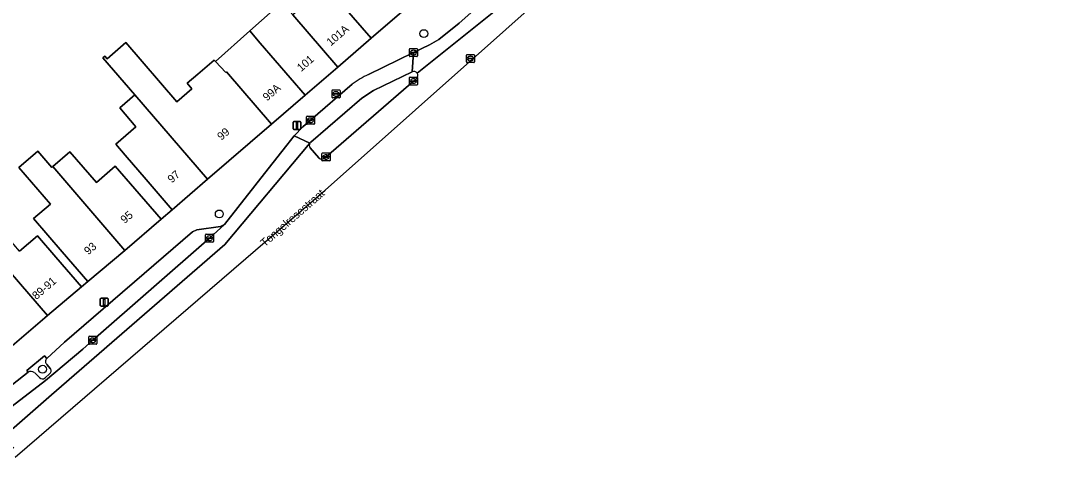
# Model space of a CAD drawing. Extents: x 161772 to 163126, y 383092 to 383917.
# Drawn here: x 162534.3 to 162665.1, y 383408.5 to 383464.9 of the extents above; entities that cross this region are included whole.
import ezdxf

# ---------------------------------------------------------------- set-up
doc = ezdxf.new("R2010")
doc.units = 0
for name, color, linetype in [('IMGEO_Boom', 7, 'Continuous'), ('IMGEO_Brandkraan', 7, 'Continuous'), ('IMGEO_Erf', 7, 'Continuous'), ('IMGEO_Fietspad_gesloten', 7, 'Continuous'), ('IMGEO_Kolk', 7, 'Continuous'), ('IMGEO_Lichtmast', 7, 'Continuous'), ('IMGEO_Openbare_ruimte_label', 7, 'Continuous'), ('IMGEO_Pand', 7, 'Continuous'), ('IMGEO_Pand_nummerreeks', 7, 'Continuous'), ('IMGEO_Parkeervlak_open', 7, 'Continuous'), ('IMGEO_Rijbaan_lokaal_gesloten', 7, 'Continuous'), ('IMGEO_Rioolput', 7, 'Continuous'), ('IMGEO_Verkeerseiland_groen', 7, 'Continuous'), ('IMGEO_Verkeerseiland_open', 7, 'Continuous'), ('IMGEO_Voetpad_open', 7, 'Continuous')]:
    doc.layers.add(name, color=color, linetype=linetype)

msp = doc.modelspace()

# ---------------------------------------------------------------- linework, layer by layer
at = {"layer": 'IMGEO_Boom'}
for centre in [(162584.63, 383463.28), (162559.08, 383440.74), (162537.01, 383421.33)]:
    msp.add_circle(centre, 0.489, dxfattribs=at)
at = {"layer": 'IMGEO_Brandkraan'}
for p, q in [((162573.23, 383456.24), (162574.09, 383456.24)), ((162573.16, 383455.31), (162573.16, 383456.17)), ((162574.09, 383455.24), (162573.23, 383455.24)), ((162573.42, 383455.73), (162573.42, 383455.75)), ((162573.46, 383455.78), (162573.86, 383455.78)), ((162573.86, 383455.7), (162573.46, 383455.7)), ((162573.67, 383455.46), (162573.64, 383455.46)), ((162573.65, 383456.02), (162573.67, 383456.02)), ((162573.9, 383455.75), (162573.9, 383455.73)), ((162574.16, 383456.17), (162574.16, 383455.31))]:
    msp.add_line(p, q, dxfattribs=at)
for points in [[(162573.23, 383456.24), (162574.09, 383456.24)], [(162573.16, 383455.31), (162573.16, 383456.17)], [(162574.09, 383455.24), (162573.23, 383455.24)], [(162574.16, 383456.17), (162574.16, 383455.31)]]:
    msp.add_lwpolyline(points, dxfattribs=at)
for centre, radius, start, end in [((162573.24, 383456.17), 0.0765, 91.552, 178.448), ((162573.24, 383456.17), 0.0765, 91.552, 178.448), ((162574.08, 383456.17), 0.0765, 1.552, 88.448), ((162574.08, 383456.17), 0.0765, 1.552, 88.448), ((162573.24, 383455.32), 0.0765, 181.552, 268.448), ((162573.24, 383455.32), 0.0765, 181.552, 268.448), ((162573.46, 383455.74), 0.0403, 85.8775, 175.7526), ((162573.45, 383455.73), 0.0366, 178.938, 274.7102), ((162573.86, 383455.75), 0.0386, 1.7309, 96.639), ((162573.86, 383455.74), 0.043, 264.8664, 352.4533), ((162574.08, 383455.32), 0.0765, 271.552, 358.448), ((162574.08, 383455.32), 0.0765, 271.552, 358.448)]:
    msp.add_arc(centre, radius, start, end, dxfattribs=at)
for centre, major_axis, ratio, start_param, end_param in [((162573.65, 383455.74), (-0.387, 0.002), 0.722429, 4.712389, 7.853982), ((162573.67, 383455.74), (-0.39, 0.002), 0.717154, 1.570796, 4.712389)]:
    msp.add_ellipse(centre, major_axis=major_axis, ratio=ratio, start_param=start_param, end_param=end_param, dxfattribs=at)
at = {"layer": 'IMGEO_Erf'}
msp.add_lwpolyline([(162534.15, 383436.08), (162536.38, 383438), (162538.67, 383435.33), (162541.88, 383431.61), (162542.68, 383432.29), (162539.46, 383436.02), (162535.89, 383440.16), (162538, 383441.98), (162534.06, 383446.56), (162536.41, 383448.58), (162538.15, 383446.56), (162538.29, 383446.67), (162540.41, 383448.51), (162543.73, 383444.66), (162546.09, 383446.7), (162548.55, 383443.86), (162551.81, 383440.07), (162553.21, 383441.27), (162549.95, 383445.06), (162547.33, 383448.1), (162546.15, 383449.47), (162548.67, 383451.64), (162546.65, 383453.99), (162548.53, 383455.61), (162544.54, 383460.24), (162544.78, 383460.45), (162545.07, 383460.11), (162547.43, 383462.15), (162553.8, 383454.76), (162555.67, 383456.36), (162555.07, 383457.07), (162556.41, 383458.22), (162558.43, 383459.96), (162558.59, 383459.8), (162562.88, 383463.61), (162566.9, 383467.17)], dxfattribs=at)
at = {"layer": 'IMGEO_Fietspad_gesloten'}
for points in [[(162576.89, 383455.22), (162578.35, 383456.17), (162583.17, 383458.49), (162583.33, 383460.91), (162577.72, 383458.18)], [(162575.68, 383456.95), (162570.47, 383452.45), (162569.53, 383451.63), (162568.44, 383450.5), (162570.38, 383449.58)], [(162570.5, 383449.72), (162576.89, 383455.22)]]:
    msp.add_lwpolyline(points, dxfattribs=at)
for centre, radius, start, end in [((162583.4, 383446.48), 13.01, 115.8975, 126.3933), ((162570.81, 383449.34), 0.489, 129.2025, 150.6211)]:
    msp.add_arc(centre, radius, start, end, dxfattribs=at)
at = {"layer": 'IMGEO_Kolk'}
for p, q in [((162582.83, 383460.48), (162582.83, 383461.33)), ((162582.9, 383461.41), (162583.76, 383461.41)), ((162583.76, 383460.41), (162582.9, 383460.41)), ((162583.09, 383460.9), (162583.09, 383460.91)), ((162583.13, 383460.95), (162583.53, 383460.95)), ((162583.52, 383460.86), (162583.13, 383460.86)), ((162583.34, 383460.63), (162583.31, 383460.63)), ((162583.32, 383461.19), (162583.34, 383461.19)), ((162583.57, 383460.91), (162583.57, 383460.9)), ((162583.83, 383461.33), (162583.83, 383460.48)), ((162582.84, 383456.92), (162582.84, 383457.78)), ((162582.91, 383457.85), (162583.77, 383457.85)), ((162583.33, 383457.63), (162583.35, 383457.63)), ((162583.84, 383457.78), (162583.84, 383456.92)), ((162583.77, 383456.85), (162582.91, 383456.85)), ((162583.1, 383457.34), (162583.1, 383457.36)), ((162583.14, 383457.39), (162583.54, 383457.39)), ((162583.54, 383457.31), (162583.14, 383457.31)), ((162583.35, 383457.07), (162583.33, 383457.07)), ((162583.58, 383457.36), (162583.58, 383457.34)), ((162569.96, 383452.02), (162569.96, 383452.87)), ((162570.04, 383452.95), (162570.89, 383452.95)), ((162570.22, 383452.44), (162570.22, 383452.45)), ((162570.66, 383452.4), (162570.26, 383452.4)), ((162570.27, 383452.49), (162570.66, 383452.49)), ((162570.45, 383452.73), (162570.48, 383452.73)), ((162570.71, 383452.45), (162570.71, 383452.44)), ((162570.97, 383452.87), (162570.97, 383452.02)), ((162570.89, 383451.95), (162570.04, 383451.95)), ((162570.47, 383452.17), (162570.45, 383452.17)), ((162571.91, 383447.43), (162571.91, 383448.28)), ((162571.99, 383448.36), (162572.84, 383448.36)), ((162572.84, 383447.36), (162571.99, 383447.36)), ((162572.17, 383447.85), (162572.17, 383447.86)), ((162572.21, 383447.9), (162572.61, 383447.9)), ((162572.61, 383447.81), (162572.21, 383447.81)), ((162572.4, 383448.14), (162572.43, 383448.14)), ((162572.42, 383447.58), (162572.4, 383447.58)), ((162572.66, 383447.86), (162572.66, 383447.85)), ((162572.91, 383448.28), (162572.91, 383447.43)), ((162557.36, 383437.28), (162557.36, 383438.14)), ((162557.44, 383438.21), (162558.29, 383438.21)), ((162557.85, 383437.99), (162557.88, 383437.99)), ((162558.36, 383438.14), (162558.36, 383437.28)), ((162558.29, 383437.21), (162557.44, 383437.21)), ((162557.62, 383437.7), (162557.62, 383437.72)), ((162558.06, 383437.67), (162557.66, 383437.67)), ((162557.67, 383437.75), (162558.06, 383437.75)), ((162557.87, 383437.43), (162557.85, 383437.43)), ((162558.11, 383437.72), (162558.11, 383437.7)), ((162542.78, 383424.53), (162542.78, 383425.38)), ((162542.86, 383425.45), (162543.71, 383425.45)), ((162543.04, 383424.95), (162543.04, 383424.96)), ((162543.48, 383424.91), (162543.08, 383424.91)), ((162543.09, 383425), (162543.48, 383425)), ((162543.27, 383425.23), (162543.3, 383425.23)), ((162543.53, 383424.96), (162543.53, 383424.95)), ((162543.78, 383425.38), (162543.78, 383424.53)), ((162543.71, 383424.45), (162542.86, 383424.45)), ((162543.29, 383424.67), (162543.27, 383424.67))]:
    msp.add_line(p, q, dxfattribs=at)
for points in [[(162582.83, 383460.48), (162582.83, 383461.33)], [(162582.9, 383461.41), (162583.76, 383461.41)], [(162583.76, 383460.41), (162582.9, 383460.41)], [(162583.83, 383461.33), (162583.83, 383460.48)], [(162582.84, 383456.92), (162582.84, 383457.78)], [(162582.91, 383457.85), (162583.77, 383457.85)], [(162583.84, 383457.78), (162583.84, 383456.92)], [(162583.77, 383456.85), (162582.91, 383456.85)], [(162569.96, 383452.02), (162569.96, 383452.87)], [(162570.04, 383452.95), (162570.89, 383452.95)], [(162570.97, 383452.87), (162570.97, 383452.02)], [(162570.89, 383451.95), (162570.04, 383451.95)], [(162571.91, 383447.43), (162571.91, 383448.28)], [(162571.99, 383448.36), (162572.84, 383448.36)], [(162572.84, 383447.36), (162571.99, 383447.36)], [(162572.91, 383448.28), (162572.91, 383447.43)], [(162557.36, 383437.28), (162557.36, 383438.14)], [(162557.44, 383438.21), (162558.29, 383438.21)], [(162558.36, 383438.14), (162558.36, 383437.28)], [(162558.29, 383437.21), (162557.44, 383437.21)], [(162542.78, 383424.53), (162542.78, 383425.38)], [(162542.86, 383425.45), (162543.71, 383425.45)], [(162543.78, 383425.38), (162543.78, 383424.53)], [(162543.71, 383424.45), (162542.86, 383424.45)]]:
    msp.add_lwpolyline(points, dxfattribs=at)
for centre, radius, start, end in [((162582.9, 383461.33), 0.0765, 91.552, 178.448), ((162582.9, 383461.33), 0.0765, 91.552, 178.448), ((162582.9, 383460.48), 0.0765, 181.552, 268.448), ((162582.9, 383460.48), 0.0765, 181.552, 268.448), ((162583.13, 383460.91), 0.0403, 85.8775, 175.7526), ((162583.12, 383460.9), 0.0366, 178.938, 274.7102), ((162583.53, 383460.91), 0.043, 264.8664, 352.4533), ((162583.53, 383460.91), 0.0386, 1.7309, 96.639), ((162583.75, 383461.33), 0.0765, 1.552, 88.448), ((162583.75, 383461.33), 0.0765, 1.552, 88.448), ((162583.75, 383460.48), 0.0765, 271.552, 358.448), ((162583.75, 383460.48), 0.0765, 271.552, 358.448), ((162582.92, 383457.77), 0.0765, 91.552, 178.448), ((162582.92, 383457.77), 0.0765, 91.552, 178.448), ((162583.76, 383457.77), 0.0765, 1.552, 88.448), ((162583.76, 383457.77), 0.0765, 1.552, 88.448), ((162582.92, 383456.92), 0.0765, 181.552, 268.448), ((162582.92, 383456.92), 0.0765, 181.552, 268.448), ((162583.14, 383457.35), 0.0403, 85.8775, 175.7526), ((162583.14, 383457.34), 0.0366, 178.938, 274.7102), ((162583.54, 383457.35), 0.0386, 1.7309, 96.639), ((162583.54, 383457.35), 0.043, 264.8664, 352.4533), ((162583.76, 383456.92), 0.0765, 271.552, 358.448), ((162583.76, 383456.92), 0.0765, 271.552, 358.448), ((162570.04, 383452.87), 0.0765, 91.552, 178.448), ((162570.04, 383452.87), 0.0765, 91.552, 178.448), ((162570.26, 383452.45), 0.0403, 85.8775, 175.7526), ((162570.26, 383452.44), 0.0366, 178.938, 274.7102), ((162570.67, 383452.45), 0.0386, 1.7309, 96.639), ((162570.66, 383452.45), 0.043, 264.8664, 352.4533), ((162570.89, 383452.87), 0.0765, 1.552, 88.448), ((162570.89, 383452.87), 0.0765, 1.552, 88.448), ((162570.04, 383452.02), 0.0765, 181.552, 268.448), ((162570.04, 383452.02), 0.0765, 181.552, 268.448), ((162570.89, 383452.02), 0.0765, 271.552, 358.448), ((162570.89, 383452.02), 0.0765, 271.552, 358.448), ((162571.99, 383448.28), 0.0765, 91.552, 178.448), ((162571.99, 383448.28), 0.0765, 91.552, 178.448), ((162571.99, 383447.43), 0.0765, 181.552, 268.448), ((162571.99, 383447.43), 0.0765, 181.552, 268.448), ((162572.21, 383447.86), 0.0403, 85.8775, 175.7526), ((162572.21, 383447.85), 0.0366, 178.938, 274.7102), ((162572.62, 383447.86), 0.0386, 1.7309, 96.639), ((162572.61, 383447.86), 0.043, 264.8664, 352.4533), ((162572.84, 383448.28), 0.0765, 1.552, 88.448), ((162572.84, 383448.28), 0.0765, 1.552, 88.448), ((162572.84, 383447.43), 0.0765, 271.552, 358.448), ((162572.84, 383447.43), 0.0765, 271.552, 358.448), ((162557.44, 383438.14), 0.0765, 91.552, 178.448), ((162557.44, 383438.14), 0.0765, 91.552, 178.448), ((162558.29, 383438.14), 0.0765, 1.552, 88.448), ((162558.29, 383438.14), 0.0765, 1.552, 88.448), ((162557.44, 383437.29), 0.0765, 181.552, 268.448), ((162557.44, 383437.29), 0.0765, 181.552, 268.448), ((162557.66, 383437.71), 0.0403, 85.8775, 175.7526), ((162557.66, 383437.7), 0.0366, 178.938, 274.7102), ((162558.07, 383437.72), 0.0386, 1.7309, 96.639), ((162558.06, 383437.71), 0.043, 264.8664, 352.4533), ((162558.29, 383437.29), 0.0765, 271.552, 358.448), ((162558.29, 383437.29), 0.0765, 271.552, 358.448), ((162542.86, 383425.38), 0.0765, 91.552, 178.448), ((162542.86, 383425.38), 0.0765, 91.552, 178.448), ((162543.08, 383424.96), 0.0403, 85.8775, 175.7526), ((162543.08, 383424.95), 0.0366, 178.938, 274.7102), ((162543.49, 383424.96), 0.0386, 1.7309, 96.639), ((162543.48, 383424.95), 0.043, 264.8664, 352.4533), ((162543.71, 383425.38), 0.0765, 1.552, 88.448), ((162543.71, 383425.38), 0.0765, 1.552, 88.448), ((162542.86, 383424.53), 0.0765, 181.552, 268.448), ((162542.86, 383424.53), 0.0765, 181.552, 268.448), ((162543.71, 383424.53), 0.0765, 271.552, 358.448), ((162543.71, 383424.53), 0.0765, 271.552, 358.448)]:
    msp.add_arc(centre, radius, start, end, dxfattribs=at)
for centre, major_axis, ratio, start_param, end_param in [((162583.32, 383460.91), (-0.387, 0.002), 0.722429, 4.712389, 7.853982), ((162583.34, 383460.91), (-0.39, 0.002), 0.717154, 1.570796, 4.712389), ((162583.33, 383457.35), (-0.387, 0.002), 0.722429, 4.712389, 7.853982), ((162583.35, 383457.35), (-0.39, 0.002), 0.717154, 1.570796, 4.712389), ((162570.45, 383452.45), (-0.387, 0.002), 0.722429, 4.712389, 7.853982), ((162570.48, 383452.45), (-0.39, 0.002), 0.717154, 1.570796, 4.712389), ((162572.4, 383447.86), (-0.387, 0.002), 0.722429, 4.712389, 7.853982), ((162572.42, 383447.86), (-0.39, 0.002), 0.717154, 1.570796, 4.712389), ((162557.85, 383437.71), (-0.387, 0.002), 0.722429, 4.712389, 7.853982), ((162557.87, 383437.71), (-0.39, 0.002), 0.717154, 1.570796, 4.712389), ((162543.27, 383424.95), (-0.387, 0.002), 0.722429, 4.712389, 7.853982), ((162543.29, 383424.95), (-0.39, 0.002), 0.717154, 1.570796, 4.712389)]:
    msp.add_ellipse(centre, major_axis=major_axis, ratio=ratio, start_param=start_param, end_param=end_param, dxfattribs=at)
at = {"layer": 'IMGEO_Lichtmast'}
for p, q in [((162568.3, 383451.39), (162568.3, 383452.19)), ((162568.3, 383452.19), (162568.3, 383451.39)), ((162568.4, 383452.29), (162569.18, 383452.29)), ((162569.18, 383452.29), (162568.4, 383452.29)), ((162569.18, 383451.29), (162568.4, 383451.29)), ((162568.4, 383451.29), (162569.18, 383451.29)), ((162569.28, 383452.19), (162569.28, 383451.39)), ((162569.28, 383451.39), (162569.28, 383452.19)), ((162544.22, 383429.31), (162544.22, 383430.11)), ((162544.22, 383430.11), (162544.22, 383429.31)), ((162544.32, 383430.21), (162545.11, 383430.21)), ((162545.11, 383430.21), (162544.32, 383430.21)), ((162545.21, 383430.11), (162545.21, 383429.31)), ((162545.21, 383429.31), (162545.21, 383430.11)), ((162545.11, 383429.21), (162544.32, 383429.21)), ((162544.32, 383429.21), (162545.11, 383429.21))]:
    msp.add_line(p, q, dxfattribs=at)
for points in [[(162568.71, 383452.17), (162568.87, 383452.17), (162568.87, 383451.42), (162568.71, 383451.42), (162568.71, 383452.17)], [(162544.64, 383430.09), (162544.79, 383430.09), (162544.79, 383429.34), (162544.64, 383429.34), (162544.64, 383430.09)]]:
    msp.add_lwpolyline(points, dxfattribs=at)
for centre, start, end in [((162568.4, 383452.19), 90, 180), ((162568.4, 383452.19), 90, 180), ((162568.4, 383451.39), 180, 270), ((162568.4, 383451.39), 180, 270), ((162569.18, 383452.19), 0, 90), ((162569.18, 383452.19), 360, 90), ((162569.18, 383451.39), 270, 0), ((162569.18, 383451.39), 270, 0), ((162544.32, 383430.11), 90, 180), ((162544.32, 383430.11), 90, 180), ((162545.11, 383430.11), 0, 90), ((162545.11, 383430.11), 360, 90), ((162544.32, 383429.31), 180, 270), ((162544.32, 383429.31), 180, 270), ((162545.11, 383429.31), 270, 0), ((162545.11, 383429.31), 270, 0)]:
    msp.add_arc(centre, 0.1, start, end, dxfattribs=at)
at = {"layer": 'IMGEO_Pand'}
for points in [[(162578.06, 383462.69), (162582.18, 383466.24), (162576.56, 383472.77), (162575.08, 383474.43), (162571.03, 383470.84), (162572.43, 383469.21)], [(162578.06, 383462.69), (162572.43, 383469.21), (162568.25, 383465.61), (162573.88, 383459.08)], [(162568.25, 383465.61), (162566.9, 383467.17), (162562.88, 383463.61), (162564.18, 383462.1), (162569.81, 383455.57), (162573.88, 383459.08)], [(162558.59, 383459.8), (162559.9, 383458.41), (162559.98, 383458.48), (162565.61, 383451.96), (162569.81, 383455.57), (162564.18, 383462.1), (162562.88, 383463.61)], [(162559.98, 383458.48), (162559.9, 383458.41), (162558.59, 383459.8), (162558.43, 383459.96), (162556.41, 383458.22), (162555.07, 383457.07), (162555.67, 383456.36), (162553.8, 383454.76), (162547.43, 383462.15), (162545.07, 383460.11), (162544.78, 383460.45), (162544.54, 383460.24), (162548.53, 383455.61), (162557.62, 383445.07), (162565.61, 383451.96)], [(162548.53, 383455.61), (162546.65, 383453.99), (162548.67, 383451.64), (162546.15, 383449.47), (162547.33, 383448.1), (162549.95, 383445.06), (162553.21, 383441.27), (162557.62, 383445.07)], [(162538.29, 383446.67), (162538.15, 383446.56), (162536.41, 383448.58), (162534.06, 383446.56), (162538, 383441.98), (162535.89, 383440.16), (162539.46, 383436.02), (162542.68, 383432.29), (162547.27, 383436.15)], [(162547.27, 383436.15), (162551.81, 383440.07), (162548.55, 383443.86), (162546.09, 383446.7), (162543.73, 383444.66), (162540.41, 383448.51), (162538.29, 383446.67)], [(162527.22, 383440.09), (162526.67, 383440.74), (162522.97, 383445.04), (162517.93, 383440.83), (162520.46, 383437.88), (162527.2, 383430.07), (162525.97, 383429.02), (162531.4, 383422.71), (162532.63, 383423.76), (162537.28, 383427.74), (162537.62, 383428.03)], [(162536.38, 383438), (162534.15, 383436.08), (162530.56, 383440.24), (162530.35, 383440.06), (162529, 383441.62), (162528.45, 383442.27), (162526.67, 383440.74), (162527.22, 383440.09), (162537.62, 383428.03), (162541.88, 383431.61), (162538.67, 383435.33)]]:
    msp.add_lwpolyline(points, close=True, dxfattribs=at)
at = {"layer": 'IMGEO_Parkeervlak_open'}
for points in [[(162526.3, 383411.45), (162526.84, 383411.86), (162537.39, 383419.93), (162542.05, 383423.82), (162543.29, 383424.95), (162557.86, 383437.71), (162559.75, 383439.42), (162559.22, 383439.16), (162556.27, 383438.76), (162555.73, 383438.5), (162539.77, 383424.7), (162537.55, 383422.67)], [(162535.2, 383420.95), (162525.77, 383413.56)], [(162536.61, 383420.28), (162535.99, 383420.91)], [(162537.56, 383421.92), (162537.99, 383421.4)], [(162537.87, 383420.74), (162537.32, 383420.24)]]:
    msp.add_lwpolyline(points, dxfattribs=at)
for centre, radius, start, end in [((162537.87, 383422.3), 0.49, 130.6188, 231.3541), ((162535.56, 383420.35), 0.7, 53.031, 121.5924), ((162537.61, 383421.13), 0.469, 302.9737, 35.1719), ((162536.99, 383420.64), 0.515, 223.436, 309.5536)]:
    msp.add_arc(centre, radius, start, end, dxfattribs=at)
at = {"layer": 'IMGEO_Rijbaan_lokaal_gesloten'}
for points in [[(162533.59, 383410.35), (162572.32, 383443.71), (162639.62, 383503.66), (162648.31, 383511.24), (162655.93, 383517.89), (162760.19, 383608.76), (162810.67, 383652.75), (162813.54, 383654.67), (162813.54, 383654.67), (162810, 383658.56), (162809.4, 383658.02), (162791.64, 383642.15), (162732.44, 383589.53), (162645.9, 383512.73), (162632.68, 383500.8), (162593.56, 383466.15), (162583.79, 383458.34)], [(162583.79, 383458.34), (162593.56, 383466.15), (162632.68, 383500.8), (162645.9, 383512.73), (162732.44, 383589.53), (162791.64, 383642.15)], [(162666.51, 383533.35), (162664.1, 383531.2), (162658.7, 383526.4), (162648.83, 383517.63), (162647.31, 383516.27), (162641.53, 383511.12), (162628.99, 383500), (162626.8, 383498.05), (162611.1, 383484.08), (162600.31, 383474.53), (162595.1, 383469.95), (162592.84, 383467.95), (162592.35, 383467.52), (162589.05, 383464.6), (162586.5, 383462.56), (162585.33, 383461.87), (162583.33, 383460.91), (162583.17, 383458.49)], [(162583.7, 383457.66), (162583.34, 383457.35), (162572.41, 383447.86), (162572.24, 383447.7)], [(162570.38, 383449.58), (162559.77, 383436.92), (162538.13, 383418.15), (162528.46, 383409.71), (162529.39, 383408.48), (162533.41, 383411.59)], [(162571.53, 383447.75), (162570.45, 383449)]]:
    msp.add_lwpolyline(points, dxfattribs=at)
msp.add_lwpolyline([(162570.38, 383449.58), (162568.44, 383450.5), (162567.52, 383449.33), (162565.18, 383446.36), (162559.75, 383439.42), (162557.86, 383437.71), (162543.29, 383424.95), (162542.05, 383423.82), (162537.39, 383419.93), (162526.84, 383411.86), (162528.46, 383409.71), (162538.13, 383418.15), (162559.77, 383436.92)], close=True, dxfattribs=at)
for centre, radius, start, end in [((162583.39, 383458.04), 0.499, 36.6781, 116.1208), ((162583.39, 383458.04), 0.497, 308.5805, 36.6139), ((162570.82, 383449.33), 0.5, 150.2327, 222.1024), ((162571.91, 383448.12), 0.533, 224.3751, 307.8679)]:
    msp.add_arc(centre, radius, start, end, dxfattribs=at)
at = {"layer": 'IMGEO_Rioolput'}
for p, q in [((162589.95, 383459.73), (162589.95, 383460.58)), ((162590.02, 383460.66), (162590.87, 383460.66)), ((162590.2, 383460.15), (162590.2, 383460.16)), ((162590.25, 383460.2), (162590.64, 383460.2)), ((162590.43, 383460.44), (162590.46, 383460.44)), ((162590.69, 383460.16), (162590.69, 383460.15)), ((162590.95, 383460.58), (162590.95, 383459.73)), ((162590.87, 383459.66), (162590.02, 383459.66)), ((162590.64, 383460.11), (162590.24, 383460.11)), ((162590.46, 383459.88), (162590.43, 383459.88))]:
    msp.add_line(p, q, dxfattribs=at)
for points in [[(162589.95, 383459.73), (162589.95, 383460.58)], [(162590.02, 383460.66), (162590.87, 383460.66)], [(162590.95, 383460.58), (162590.95, 383459.73)], [(162590.87, 383459.66), (162590.02, 383459.66)]]:
    msp.add_lwpolyline(points, dxfattribs=at)
for centre, radius, start, end in [((162590.02, 383460.58), 0.0765, 91.552, 178.448), ((162590.02, 383460.58), 0.0765, 91.552, 178.448), ((162590.24, 383460.16), 0.0403, 85.8775, 175.7526), ((162590.24, 383460.15), 0.0366, 178.938, 274.7102), ((162590.65, 383460.16), 0.0386, 1.7309, 96.639), ((162590.65, 383460.16), 0.043, 264.8664, 352.4533), ((162590.87, 383460.58), 0.0765, 1.552, 88.448), ((162590.87, 383460.58), 0.0765, 1.552, 88.448), ((162590.02, 383459.73), 0.0765, 181.552, 268.448), ((162590.02, 383459.73), 0.0765, 181.552, 268.448), ((162590.87, 383459.73), 0.0765, 271.552, 358.448), ((162590.87, 383459.73), 0.0765, 271.552, 358.448)]:
    msp.add_arc(centre, radius, start, end, dxfattribs=at)
for centre, major_axis, ratio, start_param, end_param in [((162590.43, 383460.16), (-0.387, 0.002), 0.722429, 4.712389, 7.853982), ((162590.46, 383460.16), (-0.39, 0.002), 0.717154, 1.570796, 4.712389)]:
    msp.add_ellipse(centre, major_axis=major_axis, ratio=ratio, start_param=start_param, end_param=end_param, dxfattribs=at)
at = {"layer": 'IMGEO_Verkeerseiland_groen'}
for points in [[(162537.55, 383422.67), (162537.27, 383423), (162535.03, 383421.17), (162535.2, 383420.95)], [(162535.99, 383420.91), (162536.61, 383420.28)], [(162537.99, 383421.4), (162537.56, 383421.92)], [(162537.32, 383420.24), (162537.87, 383420.74)]]:
    msp.add_lwpolyline(points, dxfattribs=at)
for centre, radius, start, end in [((162537.87, 383422.3), 0.49, 130.6188, 231.3541), ((162535.56, 383420.35), 0.7, 53.031, 121.5924), ((162537.61, 383421.13), 0.469, 302.9737, 35.1719), ((162536.99, 383420.64), 0.515, 223.436, 309.5536)]:
    msp.add_arc(centre, radius, start, end, dxfattribs=at)
at = {"layer": 'IMGEO_Verkeerseiland_open'}
for points in [[(162583.17, 383458.49), (162578.35, 383456.17), (162576.89, 383455.22), (162570.5, 383449.72)], [(162572.24, 383447.7), (162572.41, 383447.86), (162583.34, 383457.35), (162583.7, 383457.66)], [(162570.45, 383449), (162571.53, 383447.75)]]:
    msp.add_lwpolyline(points, dxfattribs=at)
for centre, radius, start, end in [((162583.39, 383458.04), 0.499, 36.6781, 116.1208), ((162583.39, 383458.04), 0.497, 308.5805, 36.6139), ((162570.81, 383449.34), 0.489, 129.2025, 150.6211), ((162570.82, 383449.33), 0.5, 150.2327, 222.1024), ((162571.91, 383448.12), 0.533, 224.3751, 307.8679)]:
    msp.add_arc(centre, radius, start, end, dxfattribs=at)
at = {"layer": 'IMGEO_Voetpad_open'}
for points in [[(162583.33, 383460.91), (162585.33, 383461.87), (162586.5, 383462.56), (162589.05, 383464.6), (162592.35, 383467.52), (162592.84, 383467.95), (162595.1, 383469.95)], [(162582.18, 383466.24), (162578.06, 383462.69), (162573.88, 383459.08), (162569.81, 383455.57), (162565.61, 383451.96), (162557.62, 383445.07), (162553.21, 383441.27), (162551.81, 383440.07), (162547.27, 383436.15), (162542.68, 383432.29), (162541.88, 383431.61), (162537.62, 383428.03), (162537.28, 383427.74), (162532.63, 383423.76)], [(162577.72, 383458.18), (162583.33, 383460.91)], [(162525.77, 383413.56), (162535.2, 383420.95), (162535.03, 383421.17), (162537.27, 383423), (162537.55, 383422.67), (162539.77, 383424.7), (162555.73, 383438.5), (162556.27, 383438.76), (162559.22, 383439.16), (162559.75, 383439.42), (162565.18, 383446.36), (162567.52, 383449.33), (162568.44, 383450.5), (162569.53, 383451.63), (162570.47, 383452.45), (162575.68, 383456.95)]]:
    msp.add_lwpolyline(points, dxfattribs=at)
msp.add_arc((162583.4, 383446.48), 13.01, 115.8975, 126.3933, dxfattribs=at)

# ---------------------------------------------------------------- texts
at = {"layer": 'IMGEO_Openbare_ruimte_label'}
msp.add_text('Tongelresestraat', height=1, rotation=41.0674, dxfattribs=at).set_placement((162564.76, 383436.57))
at = {"layer": 'IMGEO_Pand_nummerreeks'}
for s, rotation, p in [('101A', 40.7612, (162573.01, 383461.67)), ('101', 40.7586, (162569.31, 383458.47)), ('99A', 40.7685, (162565.04, 383454.79)), ('99', 40.7659, (162559.35, 383449.88)), ('97', 40.743, (162553.15, 383444.54)), ('95', 40.7619, (162547.27, 383439.48)), ('93', 40.7602, (162542.72, 383435.56)), ('89-91', 40.7488, (162536.24, 383429.97))]:
    msp.add_text(s, height=1, rotation=rotation, dxfattribs=at).set_placement(p)

doc.saveas('drawing.dxf')
